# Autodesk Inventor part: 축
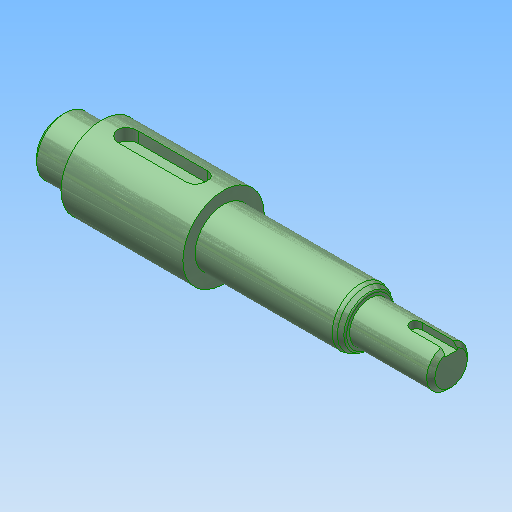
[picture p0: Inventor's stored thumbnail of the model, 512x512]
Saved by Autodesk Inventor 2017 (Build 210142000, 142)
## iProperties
Created: 2023-11
Part Number: 축
Material: 강철, 연강
Document SubType Name: Modeling
Designer: mdu-01
Density: 1 g/cm^3
Appearance: 강철(1)
Author: mdu-01
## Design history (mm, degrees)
sketch "스케치1"
  geometry: L1 (0, 0)-(96, 0); L2 (0, 0)-(0, 6); L3 (1, 7)-(10, 7); L4 (10, 7)-(10, 10); L5 (10, 10)-(40, 10); L6 (40, 10)-(40, 7); L7 (40, 7)-(73.732, 7); L8 (76, 5.711)-(76, 5); L9 (76, 5)-(95, 5); L10 (96, 4)-(96, 0); L11 (0, 6)-(1, 7); L12 (95, 5)-(96, 4); L13 (74.732, 6.732)-(75.75, 6.144); L14 (14, 10)-(14, 7); L15 (14, 7)-(36, 7); L16 (36, 7)-(36, 10); L17 (96, 3.2)-(86, 3.2); L18 (86, 3.2)-(86, 5); A1 r 0.5 centre (75.5, 5.711) between (76, 5.711) and (75.75, 6.144); A2 r 2 centre (73.732, 5) between (74.732, 6.732) and (73.732, 7); 5 further points
  constraints: 36 end point, 10 point on line, 7 parallel, 5 perpendicular, 4 point on circle, 4 tangent, 2 centre point, 2 collinear, 2 horizontal, 2 midpoint, 1 vertical alignment
  dimensions: "d0" = 96 distance of L1.start L1.end; "d1" = 14 diameter of L3 L1; "d2" = 10 distance between parallel lines of L4 L2; "d3" = 30 distance between parallel lines of L6 L4; "d4" = 20 diameter of L5 L1; "d5" = 36 distance between parallel lines of L8 L6; "d6" = 10 diameter of L9 L1; "d7" = 1 distance of L2.end point (0, 7); "d8" = 1 distance of L3.start point (0, 7) (= d7); "d9" = 1 distance of L9.end point (96, 5) (= d7); "d10" = 1 distance of L10.start point (96, 5) (= d9); "d11" = 12 diameter of point (76, 6) L1; "d12" = 30 deg angle of L13 L7; "d13" = 0.5 radius of A1; "d14" = 2 radius of A2; "d15" = 3 distance between parallel lines of L15 L5; "d16" = 22 distance between parallel lines of L16 L14; "d17" = 1.8 distance between parallel lines of L17 L9; "d18" = 10 distance between parallel lines of L18 L10
revolve "회전1" stored, may be unused: angle "d19" = 90 deg
extrude "돌출1" cut sketch "스케치1" stored distance "d20" = 5; taper "d21" = 0 deg
extrude "돌출2" cut sketch "스케치1" stored distance "d22" = 3; taper "d23" = 0 deg
fillet "모깎기1"
fillet "모깎기2"
fillet "모깎기3"
node "솔리드1"
